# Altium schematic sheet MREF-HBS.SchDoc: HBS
size A4; CompanyName: TRINAMIC; DocumentNumber: 1; SheetNumber: 1; SheetTotal: 5; Author: Indrek Rebane; DrawnBy: Indrek Rebane; Engineer: Indrek Rebane; Organization: Hedgehog OÜ; Address1: Waterloohain 5; Address2: 22769 Hamburg; Address3: Germany; Address4: tmc_info@trinamic.com
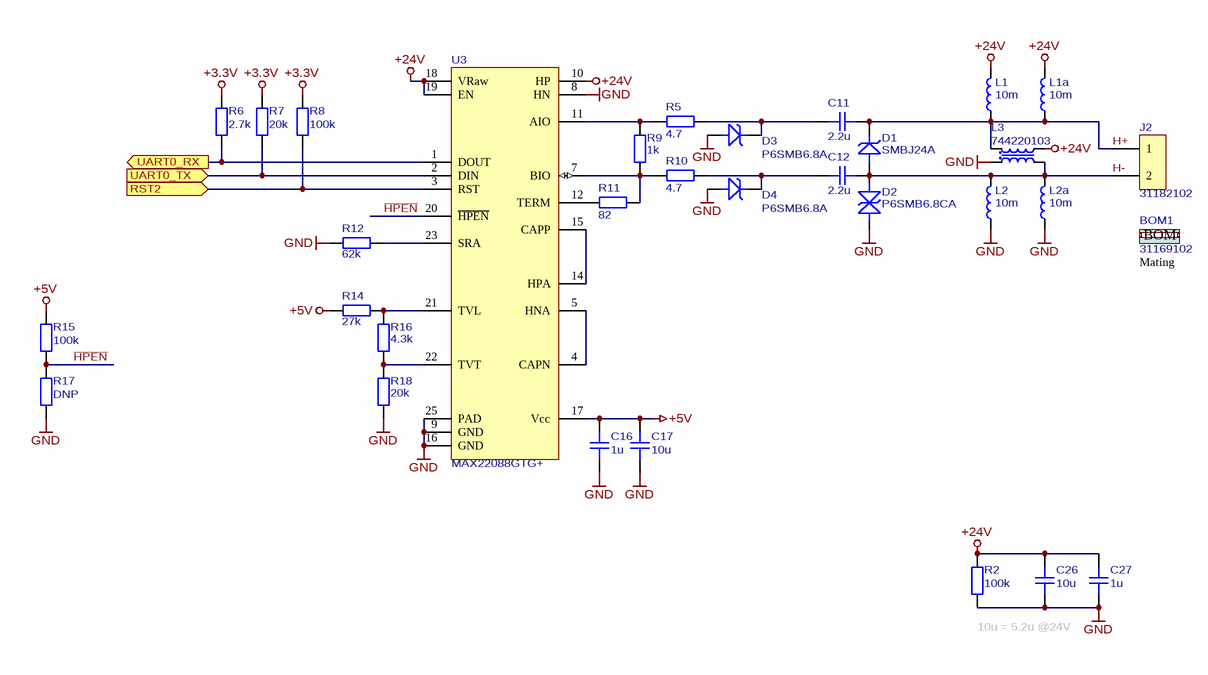
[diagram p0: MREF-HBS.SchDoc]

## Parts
BOM1  Part Number: 31169102  (hidden comment: BOM-ITEM)  (mechanical)
C11  value 2.2u  [CAPC2012N]  (hidden comment: CAPC)
C12  value 2.2u  [CAPC2012N]  (hidden comment: CAPC)
C16  value 1u  [CAPC1608N]  (hidden comment: CAPC)
C17  value 10u  [CAPC2012N]  (hidden comment: CAPC)
C26  value 10u  [CAPC3225N]  (hidden comment: CAPC)
C27  value 1u  [CAPC2012N]  (hidden comment: CAPC)
D1  Part Number: SMBJ24A  [DIOM4336X25N]  (hidden comment: TVS)
D2  Part Number: P6SMB6.8CA  [DIOM4336X25N]  (hidden comment: TVS-SYM)
D3  Part Number: P6SMB6.8A  [DIOM4336X25N]  (hidden comment: TVS)
D4  Part Number: P6SMB6.8A  [DIOM4336X25N]  (hidden comment: TVS)
J2  Part Number: 31182102  [PT11302HBBN]  (hidden comment: HDR1x2A)
L1  value 10m  [WE-LQS_8065]  (hidden comment: INDM)
L1a  value 10m  [MSS1210]  (hidden comment: INDM)
L2  value 10m  [WE-LQS_8065]  (hidden comment: INDM)
L2a  value 10m  [MSS1210]  (hidden comment: INDM)
L3  Part Number: 744220103  [WE-SL2]  (hidden comment: IND_COM_MODE2)
R2  value 100k  [RESC1005N]  (hidden comment: RESC)
R5  value 4.7  [RESC1608N]  (hidden comment: RESC)
R6  value 2.7k  [RESC1005N]  (hidden comment: RESC)
R7  value 20k  [RESC1005N]  (hidden comment: RESC)
R8  value 100k  [RESC1005N]  (hidden comment: RESC)
R9  value 1k  [RESC1005N]  (hidden comment: RESC)
R10  value 4.7  [RESC1608N]  (hidden comment: RESC)
R11  value 82  [RESC2012N]  (hidden comment: RESC)
R12  value 62k  [RESC1005N]  (hidden comment: RESC)
R14  value 27k  [RESC1005N]  (hidden comment: RESC)
R15  value 100k  [RESC1005N]  (hidden comment: RESC)
R16  value 4.3k  [RESC1005N]  (hidden comment: RESC)
R17  value DNP  [RESC1005N]  (hidden comment: RESC)
R18  value 20k  [RESC1005N]  (hidden comment: RESC)
U3  Part Number: MAX22088GTG+  [QFN50P400X400X80_HS-25N]  (hidden comment: MAX22088)

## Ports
RST2 (in), UART0_RX (out), UART0_TX (in)

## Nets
+3.3V: R6.1 R7.1 R8.1
+5V: C16.2 C17.2 R14.2 R15.1 U3.17(Vcc)
+24V: C26.2 C27.1 L1.2 L1a.2 L3.4 R2.1 U3.10(HP) U3.18(VRaw) U3.19(EN)
GND: C16.1 C17.1 C26.1 C27.2 D2.1(A) D3.2(A) D4.2(A) L2.1 L2a.1 L3.2 R2.2 R12.1 R17.2 R18.1 U3.8(HN) U3.9(GND) U3.16(GND) U3.25(PAD)
~{HPEN}: R15.2 R17.1 U3.20(~{HPEN})
H+: C11.1 D1.1(K) J2.1 L1.1 L1a.1 L3.1
H-: C12.1 D1.2(A) D2.2(K) J2.2 L2.2 L2a.2 L3.3
RST2: R8.2 U3.3(RST) ; port RST2
UART0_RX: R6.2 U3.1(DOUT) ; port UART0_RX
UART0_TX: R7.2 U3.2(DIN) ; port UART0_TX
NetC11_2: C11.2 D3.1(K) R5.1
NetC12_2: C12.2 D4.1(K) R10.1
NetR5_2: R5.2 R9.2 U3.11(AIO)
NetR9_1: R9.1 R10.2 R11.2 U3.7(BIO)
NetR11_1: R11.1 U3.12(TERM)
NetR12_2: R12.2 U3.23(SRA)
NetR14_1: R14.1 R16.2 U3.21(TVL)
NetR16_1: R16.1 R18.2 U3.22(TVT)
NetU3_4: U3.4(CAPN) U3.5(HNA)
NetU3_14: U3.14(HPA) U3.15(CAPP)

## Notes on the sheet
- (near BOM1) Mating
- 10u = 5.2u @24V

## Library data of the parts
BOM1 = 51640: BOM item; Manufacturer: Metz Connect; Id: 51640; Value: 2 pin, 3.5mm
C11 C12 = 20202: Ceramic chip capacitor; Manufacturer: Any; Part Number: 2.2u, 50V, X7R, 0805 (2012 metric) chip capacitor; Id: 20202; Voltage: 50V
C16 = 20005: Ceramic chip capacitor; Manufacturer: Any; Part Number: 1u, 16V, X5R, 0603 (1608 metric) chip capacitor; Id: 20005; Voltage: 16V
C17 = 20166: Ceramic chip capacitor; Manufacturer: Any; Part Number: 10u, 10V, X7R, 0805 (2012 metric) chip capacitor; Id: 20166; Voltage: 10V
C26 = 30010: Ceramic chip capacitor; Manufacturer: Samsung; Part Number: CL32B106KBJNNN; Id: 30010; Voltage: 50V
C27 = 20079: Ceramic chip capacitor; Manufacturer: Any; Part Number: 1u, 50V, X5R, 0805 (2012 metric) chip capacitor; Id: 20079; Voltage: 50V
D1 = 51483: TVS, Pin1 Cathode; Manufacturer: Littelfuse; Id: 51483; Value: 24V,600W
D2 = 51484: Transient Voltage Suppression (TVS) Diode; Manufacturer: Littelfuse; Id: 51484; Value: 6.8V,600W, Bidir
D3 D4 = 51475: TVS, Pin1 Cathode; Manufacturer: Littelfuse; Id: 51475; Value: 6.8V,600W
J2 = 51518: 1X2 pin connector; Manufacturer: Metz Connect; Id: 51518; Value: 2 pin, 3.5mm
L1 L2 = 60123: Molded inductor; Manufacturer: Wurth; Part Number: 74404086103; Id: 60123; Tolerance: 20%; Current: 0.2A
L1a L2a = 60125: Molded inductor; Manufacturer: Coilcraft; Part Number: MSS1210-106KE; Id: 60125; Tolerance: 10%; Current: 0.24A
L3 = 51520: Common mode inductor, pins 1 and 2 dot; Manufacturer: Wurth; Id: 51520; Type: IND; Value: 10m, 350mA
R2 R8 R15 = 10010: Chip Resistor; Manufacturer: Any; Part Number: 100k, 1%, 62mW, 0402 (1005 metric) chip resistor; Id: 10010; Tolerance: 1%; Power: 62mW
R5 R10 = 10140: Chip Resistor; Manufacturer: Any; Part Number: 4.7, 1%, 100mW, 0603 (1608 metric) chip resistor; Id: 10140; Tolerance: 1%; Power: 100mW
R6 = 10061: Chip Resistor; Manufacturer: Any; Part Number: 2.7k, 1%, 62mW, 0402 (1005 metric) chip resistor; Id: 10061; Tolerance: 1%; Power: 62mW
R7 R18 = 10083: Chip Resistor; Manufacturer: Any; Part Number: 20k, 1%, 62mW, 0402 (1005 metric) chip resistor; Id: 10083; Tolerance: 1%; Power: 62mW
R9 = 10014: Chip Resistor; Manufacturer: Any; Part Number: 1k, 1%, 62mW, 0402 (1005 metric) chip resistor; Id: 10014; Tolerance: 1%; Power: 62mW
R11 = 10446: Chip Resistor; Manufacturer: Any; Part Number: 82, 0.1%, 125mW, 0805 (2012 metric) chip resistor; Id: 10446; Tolerance: 0.1%; Power: 125mW
R12 = 10447: Chip Resistor; Manufacturer: Any; Part Number: 62k, 1%, 62mW, 0402 (1005 metric) chip resistor; Id: 10447; Tolerance: 1%; Power: 62mW
R14 = 10241: Chip Resistor; Manufacturer: Any; Part Number: 27k, 1%, 62mW, 0402 (1005 metric) chip resistor; Id: 10241; Tolerance: 1%; Power: 62mW
R16 = 10448: Chip Resistor; Manufacturer: Any; Part Number: 4.3k, 1%, 62mW, 0402 (1005 metric) chip resistor; Id: 10448; Tolerance: 1%; Power: 62mW
R17 = 40006: Chip Resistor; Id: 40006
U3 = 51469: Home Bus System (HBS) Compatible / Transceiver; Manufacturer: Maxim Integrated; Id: 51469; Value: Home Bus System transceiver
